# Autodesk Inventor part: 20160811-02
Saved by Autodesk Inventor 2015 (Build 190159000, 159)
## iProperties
Created: 2016-08
Part Number: 20160811-02
Material: Hliník 6061
Document SubType Name: Modeling
Designer: navara
Density: 2.7 g/cm^3
Appearance: Hliník – plochý
Author: navara
Beppe: 20160811-02.ipt
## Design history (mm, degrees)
feature "Base1"
node "Těleso1"
